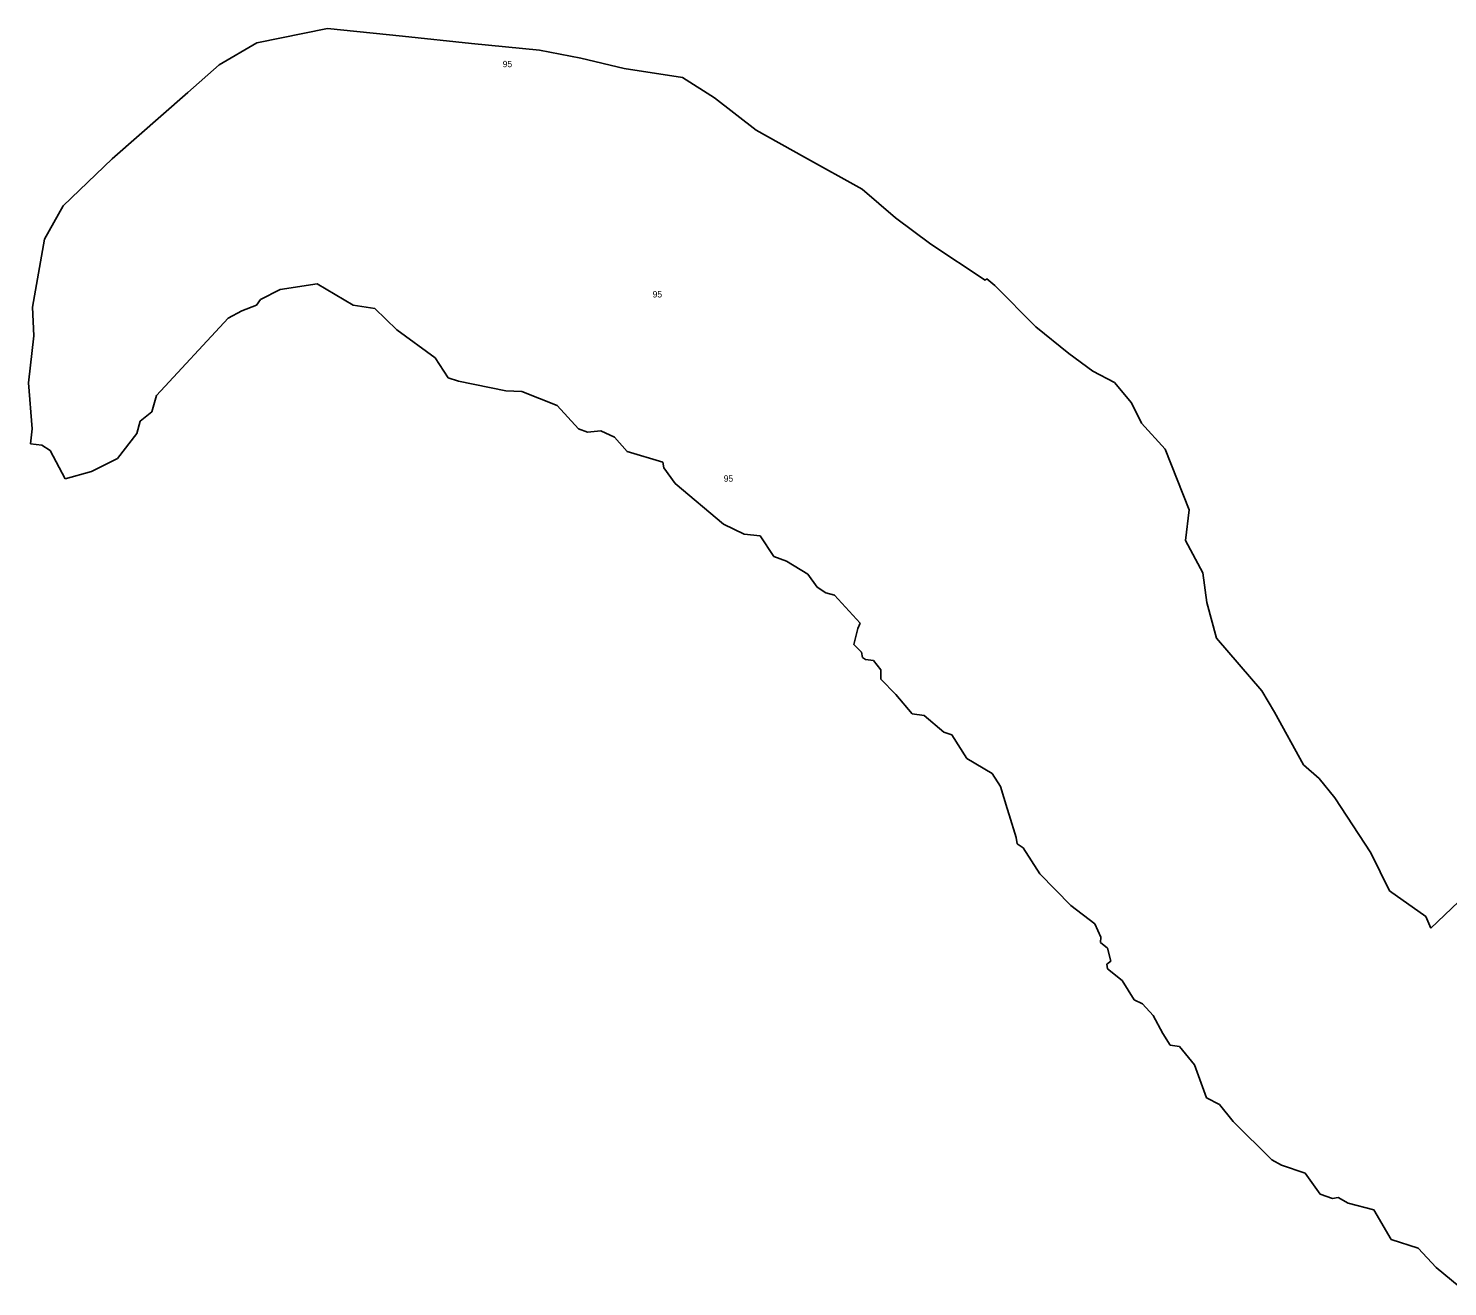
# Model space of a CAD drawing. Extents: x -786993 to -782941, y -974639 to -970914.
# Drawn here: x -786993 to -784974, y -973097 to -971307 of the extents above; entities that cross this region are included whole.
import ezdxf

# ---------------------------------------------------------------- set-up
doc = ezdxf.new("R2010")
doc.units = 0
doc.layers.add('Vrstva 13', color=7, linetype='Continuous')
doc.layers.add('Vrstva 24', color=7, linetype='Continuous')

msp = doc.modelspace()

# ---------------------------------------------------------------- linework, layer by layer
at = {"layer": 'Vrstva 13'}
for p, q in [((-786668.34, -971327.33), (-786567.74, -971306.6)), ((-786567.74, -971306.6), (-786461.29, -971317.88)), ((-786721.86, -971358.7), (-786668.34, -971327.33)), ((-786461.29, -971317.88), (-786362.98, -971327.98)), ((-786362.98, -971327.98), (-786266.45, -971337.7)), ((-786266.45, -971337.7), (-786207.55, -971349.12)), ((-786207.55, -971349.12), (-786145.9, -971363.68)), ((-786766.53, -971397.68), (-786721.86, -971358.7)), ((-786145.9, -971363.68), (-786062.9, -971376.54)), ((-786062.9, -971376.54), (-786017.45, -971405.27)), ((-786874.09, -971492.16), (-786766.53, -971397.68)), ((-786017.45, -971405.27), (-785957.98, -971451.59)), ((-785957.98, -971451.59), (-785889.26, -971489.84)), ((-786943.8, -971559.09), (-786874.09, -971492.16)), ((-785889.26, -971489.84), (-785807.51, -971535.19)), ((-785807.51, -971535.19), (-785759.95, -971576.2)), ((-786970.36, -971606.59), (-786943.8, -971559.09)), ((-785759.95, -971576.2), (-785709.76, -971613.47)), ((-786987.67, -971703.4), (-786970.36, -971606.59)), ((-785709.76, -971613.47), (-785632.16, -971664.78)), ((-786635.21, -971678.28), (-786582.59, -971669.89)), ((-786582.59, -971669.89), (-786531.4, -971700.43)), ((-785632.16, -971664.78), (-785630.22, -971663.08)), ((-785630.22, -971663.08), (-785618.75, -971672.66)), ((-785618.75, -971672.66), (-785560.47, -971731.32)), ((-786668.99, -971700.45), (-786663.39, -971692.29)), ((-786663.39, -971692.29), (-786635.21, -971678.28)), ((-786985.57, -971744.08), (-786987.67, -971703.4)), ((-786709.15, -971718.72), (-786690.02, -971708.74)), ((-786690.02, -971708.74), (-786668.99, -971700.45)), ((-786531.4, -971700.43), (-786500.73, -971705.2)), ((-786500.73, -971705.2), (-786469.19, -971735.52)), ((-786811.09, -971828.77), (-786709.15, -971718.72)), ((-786469.19, -971735.52), (-786414.95, -971775.3)), ((-785560.47, -971731.32), (-785513.51, -971769.11)), ((-786993.44, -971811), (-786985.57, -971744.08)), ((-786414.95, -971775.3), (-786396.36, -971803.95)), ((-785513.51, -971769.11), (-785479.12, -971794.38)), ((-785479.12, -971794.38), (-785448.18, -971810.39)), ((-786988.22, -971876.28), (-786993.44, -971811)), ((-786396.36, -971803.95), (-786381.74, -971808.39)), ((-786381.74, -971808.39), (-786314.43, -971822.51)), ((-785448.18, -971810.39), (-785423.96, -971839.59)), ((-786817.61, -971852.03), (-786811.09, -971828.77)), ((-786314.43, -971822.51), (-786291.29, -971823.39)), ((-786291.29, -971823.39), (-786241.05, -971843)), ((-786834.63, -971865.57), (-786817.61, -971852.03)), ((-786241.05, -971843), (-786211.1, -971876.37)), ((-785423.96, -971839.59), (-785409.79, -971868.33)), ((-786990.25, -971897.87), (-786988.22, -971876.28)), ((-786839.14, -971883.04), (-786834.63, -971865.57)), ((-786211.1, -971876.37), (-786198.23, -971881.25)), ((-786198.23, -971881.25), (-786179.09, -971879.06)), ((-786179.09, -971879.06), (-786159.69, -971888.3)), ((-785409.79, -971868.33), (-785376.2, -971905.41)), ((-786990.25, -971897.87), (-786974.19, -971899.63)), ((-786974.19, -971899.63), (-786962.41, -971907.2)), ((-786866.65, -971918.85), (-786839.14, -971883.04)), ((-786159.69, -971888.3), (-786141.51, -971908.73)), ((-786962.41, -971907.2), (-786941.01, -971947.67)), ((-786903.62, -971936.9), (-786866.65, -971918.85)), ((-786141.51, -971908.73), (-786091.13, -971923.98)), ((-785376.2, -971905.41), (-785342.25, -971991.56)), ((-786941.01, -971947.67), (-786903.62, -971936.9)), ((-786091.13, -971923.98), (-786089.43, -971931.9)), ((-786089.43, -971931.9), (-786073.37, -971954.27)), ((-786073.37, -971954.27), (-786004.39, -972012.07)), ((-785342.25, -971991.56), (-785347.24, -972035.13)), ((-786004.39, -972012.07), (-785975.12, -972026.13)), ((-785975.12, -972026.13), (-785952.6, -972028.68)), ((-785952.6, -972028.68), (-785932.76, -972057.97)), ((-785347.24, -972035.13), (-785322.7, -972081.19)), ((-785932.76, -972057.97), (-785914.78, -972064.74)), ((-785914.78, -972064.74), (-785884.58, -972083.02)), ((-785322.7, -972081.19), (-785316.92, -972123.57)), ((-785884.58, -972083.02), (-785871.35, -972101.56)), ((-785871.35, -972101.56), (-785858.84, -972109.86)), ((-785858.84, -972109.86), (-785846.58, -972113.02)), ((-785846.58, -972113.02), (-785810.25, -972153.05)), ((-785316.92, -972123.57), (-785303.15, -972174.24)), ((-785813.31, -972160.48), (-785819.04, -972183.42)), ((-785810.25, -972153.05), (-785813.31, -972160.48)), ((-785303.15, -972174.24), (-785238.6, -972249.43)), ((-785819.04, -972183.42), (-785808.05, -972194.02)), ((-785808.05, -972194.02), (-785806.78, -972201.66)), ((-785806.78, -972201.66), (-785802.59, -972204.83)), ((-785802.59, -972204.83), (-785791.24, -972206.07)), ((-785791.24, -972206.07), (-785780.96, -972219.48)), ((-785780.96, -972219.48), (-785780.73, -972232.52)), ((-785780.73, -972232.52), (-785759.51, -972254.56)), ((-785759.51, -972254.56), (-785736.15, -972281.94)), ((-785238.6, -972249.43), (-785220.76, -972279.62)), ((-785736.15, -972281.94), (-785719.19, -972284.55)), ((-785220.76, -972279.62), (-785179.3, -972354.67)), ((-785719.19, -972284.55), (-785691.17, -972308.21)), ((-785691.17, -972308.21), (-785679.96, -972311.63)), ((-785679.96, -972311.63), (-785658.35, -972345.34)), ((-785658.35, -972345.34), (-785622.49, -972366.76)), ((-785179.3, -972354.67), (-785157.27, -972374.09)), ((-785622.49, -972366.76), (-785610.72, -972385.34)), ((-785157.27, -972374.09), (-785135.09, -972401.65)), ((-785610.72, -972385.34), (-785601.26, -972416.79)), ((-785135.09, -972401.65), (-785083.8, -972479.73)), ((-785601.26, -972416.79), (-785598.02, -972425.56)), ((-785598.02, -972425.56), (-785588.34, -972458.11)), ((-785588.34, -972458.11), (-785586.96, -972467.14)), ((-785586.96, -972467.14), (-785578.3, -972472.82)), ((-785578.3, -972472.82), (-785554.43, -972509.8)), ((-785083.8, -972479.73), (-785057.04, -972533.67)), ((-784998.3, -972586.82), (-784872.63, -972466.94)), ((-785554.43, -972509.8), (-785510.65, -972554.76)), ((-785057.04, -972533.67), (-785005.62, -972570.15)), ((-785510.65, -972554.76), (-785476.15, -972580.69)), ((-785476.15, -972580.69), (-785467.85, -972599.76)), ((-785005.62, -972570.15), (-784998.3, -972586.82)), ((-785467.85, -972599.76), (-785468.38, -972607.13)), ((-785468.38, -972607.13), (-785458.37, -972615.18)), ((-785458.37, -972615.18), (-785453.6, -972633.67)), ((-785453.6, -972633.67), (-785459.49, -972638.22)), ((-785459.49, -972638.22), (-785458.54, -972644.66)), ((-785458.54, -972644.66), (-785437.62, -972661.56)), ((-785437.62, -972661.56), (-785420.22, -972689.08)), ((-785420.22, -972689.08), (-785408.58, -972694.54)), ((-785408.58, -972694.54), (-785393.36, -972710.96)), ((-785393.36, -972710.96), (-785379.59, -972737.04)), ((-785379.59, -972737.04), (-785369.18, -972753.57)), ((-785369.18, -972753.57), (-785355.94, -972755.46)), ((-785355.94, -972755.46), (-785334.76, -972781.52)), ((-785334.76, -972781.52), (-785317.5, -972828.41)), ((-785317.5, -972828.41), (-785299.02, -972837.73)), ((-785299.02, -972837.73), (-785279.43, -972861.84)), ((-785279.43, -972861.84), (-785224.77, -972916.45)), ((-785224.77, -972916.45), (-785210.92, -972923.96)), ((-785210.92, -972923.96), (-785176.92, -972935.56)), ((-785176.92, -972935.56), (-785155.6, -972965.48)), ((-785155.6, -972965.48), (-785138.13, -972971.45)), ((-785138.13, -972971.45), (-785130.32, -972969.96)), ((-785130.32, -972969.96), (-785116.05, -972978.26)), ((-785116.05, -972978.26), (-785079.66, -972987.87)), ((-785079.66, -972987.87), (-785054.92, -973029.95)), ((-785054.92, -973029.95), (-785016.2, -973042.04)), ((-785016.2, -973042.04), (-784991, -973069.56)), ((-784991, -973069.56), (-784957.99, -973096.98))]:
    msp.add_line(p, q, dxfattribs=at)

# ---------------------------------------------------------------- texts
at = {"layer": 'Vrstva 24'}
for p in [(-786318.688, -971361.838), (-786105.338, -971689.498), (-786004.278, -971951.618)]:
    msp.add_text('95', height=9, dxfattribs=at).set_placement(p)

doc.saveas('drawing.dxf')
